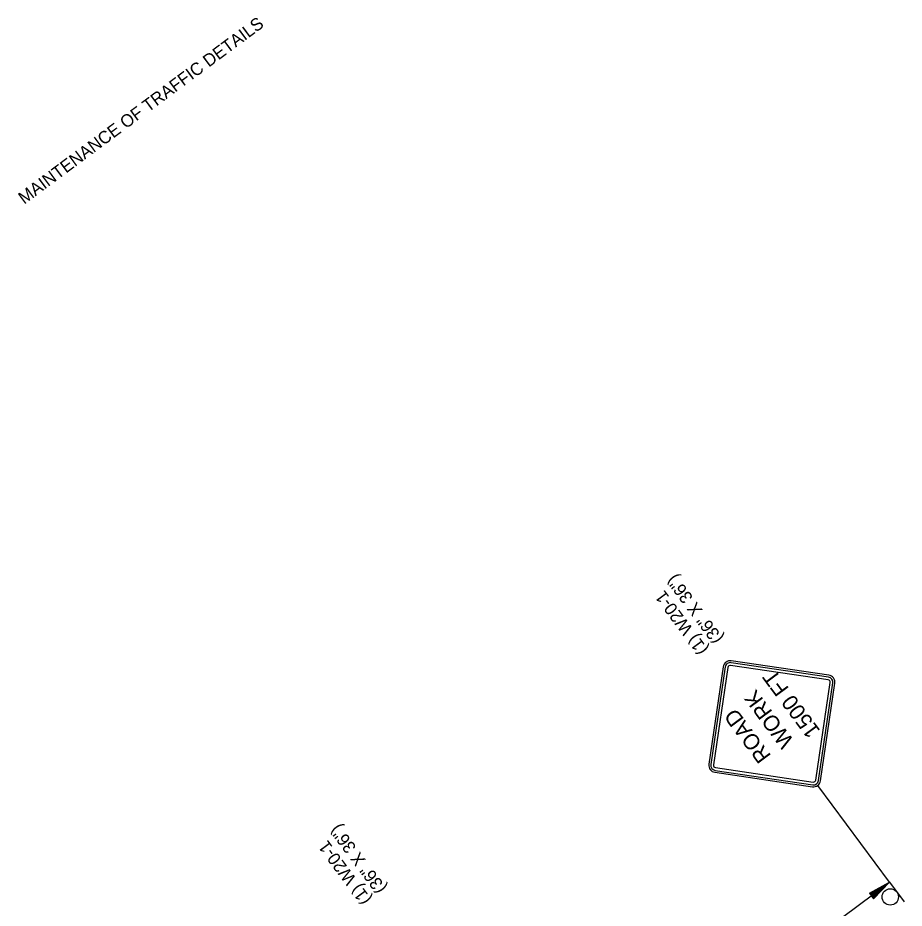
# Model space of a CAD drawing. Extents: x -238 to 1487, y -1123 to 446.
# Drawn here: x 805.7 to 1230.2, y 19.3 to 445.7 of the extents above; entities that cross this region are included whole.
import ezdxf

# ---------------------------------------------------------------- set-up
doc = ezdxf.new("R2010")
doc.units = 0
for name, color, linetype in [('P_TC_Signs_Temporary', 7, 'Continuous'), ('R_Border', 7, 'Continuous'), ('R_Border Prem', 7, 'Continuous'), ('R_Draft', 7, 'Continuous'), ('STAMP', 7, 'Continuous')]:
    doc.layers.add(name, color=color, linetype=linetype)

msp = doc.modelspace()

# ---------------------------------------------------------------- linework, layer by layer
at = {"layer": 'P_TC_Signs_Temporary'}
for p, q in [((1193.98, 129.97), (1147.23, 136.87)), ((1194.11, 130.89), (1147.37, 137.8)), ((1143.54, 134.96), (1136.63, 88.21)), ((1144.47, 134.82), (1137.56, 88.08)), ((1145.77, 134.63), (1138.86, 87.88)), ((1193.79, 128.67), (1147.04, 135.57)), ((1187.83, 80.65), (1194.73, 127.39)), ((1189.13, 80.46), (1196.03, 127.2)), ((1190.05, 80.32), (1196.96, 127.06)), ((1139.62, 85.31), (1186.36, 78.4)), ((1139.81, 86.61), (1186.55, 79.7)), ((1139.48, 84.38), (1186.22, 77.47))]:
    msp.add_line(p, q, dxfattribs=at)
for centre, radius, start, end in [((1146.88, 134.46), 3.38, 81.5953, 171.5953), ((1146.88, 134.46), 2.44, 81.5953, 171.5953), ((1146.88, 134.46), 1.12, 81.5953, 171.5953), ((1193.62, 127.56), 1.13, 351.5953, 81.5953), ((1193.62, 127.56), 2.44, 351.5953, 81.5953), ((1193.62, 127.56), 3.38, 351.5953, 81.5953), ((1139.97, 87.72), 3.38, 171.5953, 261.5953), ((1139.97, 87.72), 2.44, 171.5953, 261.5953), ((1139.97, 87.72), 1.13, 171.5953, 261.5953), ((1186.71, 80.81), 3.38, 261.5953, 351.5953), ((1186.71, 80.81), 2.44, 261.5953, 351.5953), ((1186.71, 80.81), 1.12, 261.5953, 351.5953)]:
    msp.add_arc(centre, radius, start, end, dxfattribs=at)
at = {"layer": 'R_Draft'}
for p, q in [((1223.15, 31.74), (1188.73, 78.1)), ((1062.58, -87.49), (1223.15, 31.74)), ((1213.53, 26.41), (1223.15, 31.74)), ((1213.69, 26.2), (1221.71, 30.63)), ((1215.35, 24.04), (1221.71, 30.63)), ((1215.52, 23.82), (1223.15, 31.74)), ((1213.53, 26.41), (1215.52, 23.82)), ((1213.87, 25.97), (1220.23, 29.5)), ((1214.03, 25.76), (1218.79, 28.39)), ((1214.2, 25.54), (1217.33, 27.27)), ((1214.36, 25.32), (1215.89, 26.16)), ((1214.68, 24.91), (1215.89, 26.16)), ((1214.85, 24.69), (1217.33, 27.27)), ((1215.01, 24.47), (1218.79, 28.39)), ((1215.18, 24.26), (1220.23, 29.5))]:
    msp.add_line(p, q, dxfattribs=at)
at = {"layer": 'STAMP'}
msp.add_line((1223.15, 31.74), (1230.15, 22.3), dxfattribs=at)
msp.add_circle((1223.51, 24.69), 3.92, dxfattribs=at)

# ---------------------------------------------------------------- texts
at = {"layer": 'P_TC_Signs_Temporary'}
for s, p in [('1500 FT', (1190.24, 104.29)), ('WORK', (1177.65, 99.41)), (' ROAD ', (1168.36, 90.08))]:
    msp.add_text(s, height=7.5, rotation=126.5953, dxfattribs=at).set_placement(p)
at = {"layer": 'R_Border'}
msp.add_text('MAINTENANCE OF TRAFFIC DETAILS', height=6, rotation=36.5953, dxfattribs=at).set_placement((808.79, 356.2))
at = {"layer": 'R_Border Prem'}
for s, p in [('(36" X 36")', (1143.75, 148.66)), ('(1) W20-1', (1136.52, 143.3)), ('(36" X 36")', (982.53, 28.96)), ('(1) W20-1', (975.31, 23.59))]:
    msp.add_text(s, height=6, rotation=126.5953, dxfattribs=at).set_placement(p)

doc.saveas('drawing.dxf')
